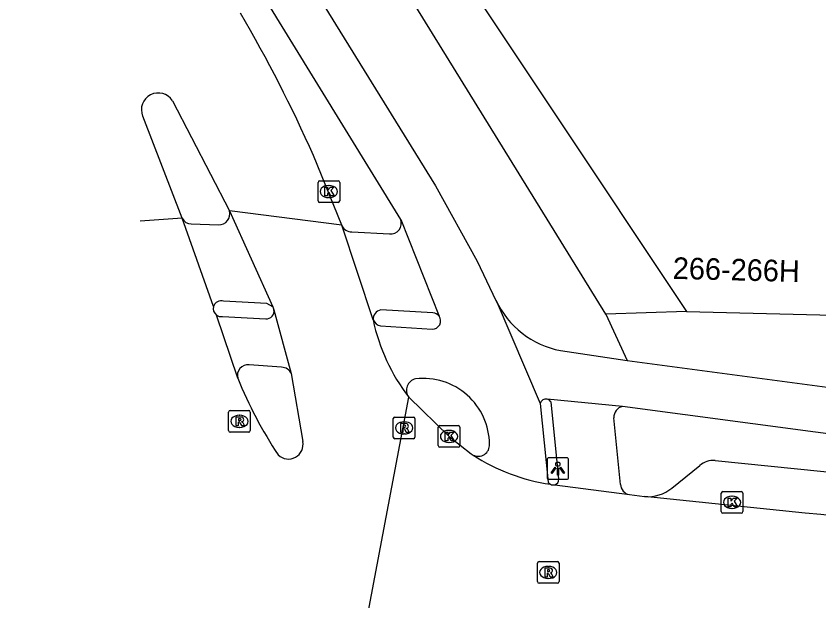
# Model space of a CAD drawing. Extents: x 158087 to 159494, y 382905 to 383981.
# Drawn here: x 158116.14 to 158153.26, y 383217.91 to 383244.96 of the extents above; entities that cross this region are included whole.
import ezdxf

# ---------------------------------------------------------------- set-up
doc = ezdxf.new("R2010")
doc.units = 0
for name, color, linetype in [('IMGEO_Fietspad_gesloten', 7, 'Continuous'), ('IMGEO_Kolk', 7, 'Continuous'), ('IMGEO_Lichtpunt', 7, 'Continuous'), ('IMGEO_Pand', 7, 'Continuous'), ('IMGEO_Pand_nummerreeks', 7, 'Continuous'), ('IMGEO_Parkeervlak_open', 7, 'Continuous'), ('IMGEO_Rijbaan_lokaal_gesloten', 7, 'Continuous'), ('IMGEO_Rioolput', 7, 'Continuous'), ('IMGEO_Voetpad_open', 7, 'Continuous')]:
    doc.layers.add(name, color=color, linetype=linetype)

msp = doc.modelspace()

# ---------------------------------------------------------------- linework, layer by layer
at = {"layer": 'IMGEO_Fietspad_gesloten'}
for points in [[(158118.441, 383264.758), (158135.528, 383237.105), (158137.451, 383233.617), (158138.325, 383231.809)], [(158133.922, 383235.542), (158116.135, 383264.493)], [(158133.922, 383235.542), (158135.691, 383231.086)], [(158138.325, 383231.809), (158138.329, 383231.797), (158140.364, 383227.042)], [(158125.678, 383231.065), (158127.681, 383230.961)], [(158132.979, 383230.63), (158135.368, 383230.486)], [(158141.305, 383229.487), (158144.391, 383229.036)], [(158144.391, 383229.036), (158160.112, 383226.941)], [(158128.413, 383228.717), (158126.917, 383228.829)], [(158144.169, 383226.91), (158140.686, 383227.24)], [(158140.364, 383227.042), (158140.74, 383223.411)], [(158159.127, 383224.909), (158144.169, 383226.91)]]:
    msp.add_lwpolyline(points, dxfattribs=at)
for centre, radius, start, end in [((158142.087, 383233.564), 4.151, 205.007, 259.142), ((158127.716, 383231.309), 0.349, 264.2417, 10.9635), ((158125.616, 383231.424), 0.364, 232.9851, 279.8076), ((158133.12, 383231.148), 0.537, 207.0122, 254.7617), ((158135.394, 383230.859), 0.374, 266.0798, 37.3301), ((158126.861, 383228.339), 0.494, 83.4339, 195.5759), ((158128.41, 383228.223), 0.494, 23.7357, 89.6533), ((158134.958, 383225.13), 3.071, 0.5018, 96.498), ((158134.721, 383227.655), 0.537, 101.7854, 216.3307), ((158140.629, 383226.972), 0.274, 77.9971, 165.1782), ((158137.503, 383225.129), 0.526, 243.1997, 3.0642), ((158140.974, 383223.54), 0.268, 208.7973, 240.0793)]:
    msp.add_arc(centre, radius, start, end, dxfattribs=at)
at = {"layer": 'IMGEO_Kolk'}
for p, q in [((158130.097, 383236.414), (158130.097, 383237.266)), ((158130.172, 383237.34), (158131.024, 383237.34)), ((158130.585, 383237.12), (158130.61, 383237.12)), ((158131.098, 383237.266), (158131.098, 383236.414)), ((158130.608, 383236.56), (158130.583, 383236.56)), ((158131.024, 383236.34), (158130.172, 383236.34)), ((158135.728, 383226.019), (158136.58, 383226.019)), ((158135.653, 383225.093), (158135.653, 383225.945)), ((158136.141, 383225.799), (158136.166, 383225.799)), ((158136.654, 383225.945), (158136.654, 383225.093)), ((158136.164, 383225.239), (158136.139, 383225.239)), ((158136.58, 383225.019), (158135.728, 383225.019)), ((158148.74, 383222.045), (158148.74, 383222.897)), ((158148.815, 383222.971), (158149.667, 383222.971)), ((158149.228, 383222.751), (158149.253, 383222.751)), ((158149.741, 383222.897), (158149.741, 383222.045)), ((158149.667, 383221.971), (158148.815, 383221.971)), ((158149.251, 383222.191), (158149.226, 383222.191))]:
    msp.add_line(p, q, dxfattribs=at)
for points in [[(158130.097, 383236.414), (158130.097, 383237.266)], [(158130.172, 383237.34), (158131.024, 383237.34)], [(158131.098, 383237.266), (158131.098, 383236.414)], [(158130.418, 383237.04), (158130.541, 383237.04), (158130.541, 383236.889), (158130.671, 383237.04), (158130.835, 383237.04), (158130.689, 383236.889), (158130.842, 383236.64), (158130.69, 383236.64), (158130.605, 383236.804), (158130.541, 383236.737), (158130.541, 383236.64), (158130.418, 383236.64), (158130.418, 383237.04)], [(158131.024, 383236.34), (158130.172, 383236.34)], [(158135.728, 383226.019), (158136.58, 383226.019)], [(158135.653, 383225.093), (158135.653, 383225.945)], [(158135.974, 383225.719), (158136.097, 383225.719), (158136.097, 383225.568), (158136.227, 383225.719), (158136.391, 383225.719), (158136.245, 383225.568), (158136.398, 383225.319), (158136.246, 383225.319), (158136.161, 383225.483), (158136.097, 383225.416), (158136.097, 383225.319), (158135.974, 383225.319), (158135.974, 383225.719)], [(158136.654, 383225.945), (158136.654, 383225.093)], [(158136.58, 383225.019), (158135.728, 383225.019)], [(158148.74, 383222.045), (158148.74, 383222.897)], [(158148.815, 383222.971), (158149.667, 383222.971)], [(158149.061, 383222.671), (158149.184, 383222.671), (158149.184, 383222.52), (158149.314, 383222.671), (158149.478, 383222.671), (158149.332, 383222.52), (158149.485, 383222.271), (158149.333, 383222.271), (158149.248, 383222.435), (158149.184, 383222.368), (158149.184, 383222.271), (158149.061, 383222.271), (158149.061, 383222.671)], [(158149.741, 383222.897), (158149.741, 383222.045)], [(158149.667, 383221.971), (158148.815, 383221.971)]]:
    msp.add_lwpolyline(points, dxfattribs=at)
for centre, start, end in [((158130.174, 383237.264), 91.552, 178.448), ((158130.174, 383237.264), 91.552, 178.448), ((158131.022, 383237.264), 1.552, 88.448), ((158131.022, 383237.264), 1.552, 88.448), ((158130.174, 383236.416), 181.552, 268.448), ((158130.174, 383236.416), 181.552, 268.448), ((158131.022, 383236.416), 271.552, 358.448), ((158131.022, 383236.416), 271.552, 358.448), ((158135.73, 383225.943), 91.552, 178.448), ((158135.73, 383225.943), 91.552, 178.448), ((158136.578, 383225.943), 1.552, 88.448), ((158136.578, 383225.943), 1.552, 88.448), ((158135.73, 383225.095), 181.552, 268.448), ((158135.73, 383225.095), 181.552, 268.448), ((158136.578, 383225.095), 271.552, 358.448), ((158136.578, 383225.095), 271.552, 358.448), ((158148.817, 383222.895), 91.552, 178.448), ((158148.817, 383222.895), 91.552, 178.448), ((158149.665, 383222.895), 1.552, 88.448), ((158149.665, 383222.895), 1.552, 88.448), ((158148.817, 383222.047), 181.552, 268.448), ((158148.817, 383222.047), 181.552, 268.448), ((158149.665, 383222.047), 271.552, 358.448), ((158149.665, 383222.047), 271.552, 358.448)]:
    msp.add_arc(centre, 0.0765, start, end, dxfattribs=at)
for centre, major_axis, ratio, start_param, end_param in [((158130.584, 383236.84), (-0.387, 0.002), 0.722429, 4.712389, 7.853982), ((158130.609, 383236.84), (-0.39, 0.002), 0.717154, 1.570796, 4.712389), ((158136.14, 383225.519), (-0.387, 0.002), 0.722429, 4.712389, 7.853982), ((158136.165, 383225.519), (-0.39, 0.002), 0.717154, 1.570796, 4.712389), ((158149.227, 383222.471), (-0.387, 0.002), 0.722429, 4.712389, 7.853982), ((158149.252, 383222.471), (-0.39, 0.002), 0.717154, 1.570796, 4.712389)]:
    msp.add_ellipse(centre, major_axis=major_axis, ratio=ratio, start_param=start_param, end_param=end_param, dxfattribs=at)
at = {"layer": 'IMGEO_Lichtpunt'}
for p, q in [((158141.588, 383224.533), (158140.78, 383224.533)), ((158141.588, 383224.533), (158140.78, 383224.533)), ((158140.686, 383224.438), (158140.686, 383223.631)), ((158140.686, 383224.438), (158140.686, 383223.631)), ((158141.682, 383223.631), (158141.682, 383224.438)), ((158141.682, 383223.631), (158141.682, 383224.438)), ((158140.78, 383223.537), (158141.588, 383223.537)), ((158140.78, 383223.537), (158141.588, 383223.537))]:
    msp.add_line(p, q, dxfattribs=at)
for points in [[(158141.06, 383224.102), (158141.099, 383224.074), (158140.911, 383223.812), (158140.873, 383223.839), (158141.06, 383224.102)], [(158141.162, 383224.054), (158141.209, 383224.054), (158141.209, 383223.732), (158141.162, 383223.732), (158141.162, 383224.054)], [(158141.272, 383224.074), (158141.31, 383224.101), (158141.497, 383223.839), (158141.458, 383223.811), (158141.272, 383224.074)]]:
    msp.add_lwpolyline(points, dxfattribs=at)
msp.add_circle((158141.185, 383224.236), 0.0994, dxfattribs=at)
for centre, start, end in [((158140.78, 383224.438), 90, 180), ((158140.78, 383224.438), 90, 180), ((158141.588, 383224.438), 0, 90), ((158141.588, 383224.438), 0, 90), ((158140.78, 383223.631), 180, 270), ((158140.78, 383223.631), 180, 270), ((158141.588, 383223.631), 270, 0), ((158141.588, 383223.631), 270, 360)]:
    msp.add_arc(centre, 0.0946, start, end, dxfattribs=at)
at = {"layer": 'IMGEO_Pand'}
for points in [[(158139.526, 383253.098), (158138.355, 383252.86), (158133.459, 383251.844), (158134.686, 383250), (158147.132, 383231.289)], [(158147.132, 383231.289), (158155.144, 383231.088)]]:
    msp.add_lwpolyline(points, dxfattribs=at)
at = {"layer": 'IMGEO_Parkeervlak_open'}
for points in [[(158146.459, 383223.131), (158147.745, 383224.182)], [(158148.453, 383224.408), (158153.476, 383223.894), (158158.929, 383223.306)]]:
    msp.add_lwpolyline(points, dxfattribs=at)
for centre, radius, start, end in [((158148.392, 383223.378), 1.031, 86.5877, 128.8194), ((158145.337, 383224.515), 1.782, 265.3753, 309.0336)]:
    msp.add_arc(centre, radius, start, end, dxfattribs=at)
at = {"layer": 'IMGEO_Rijbaan_lokaal_gesloten'}
for points in [[(158123.369, 383241.035), (158126, 383235.945)], [(158123.817, 383235.606), (158121.989, 383240.327)], [(158131.191, 383235.28), (158129.884, 383238.502)], [(158126, 383235.945), (158128.003, 383231.508)], [(158131.191, 383235.28), (158126, 383235.945)], [(158123.817, 383235.606), (158121.873, 383235.473)], [(158125.263, 383231.52), (158123.817, 383235.606)], [(158132.642, 383230.904), (158131.191, 383235.28)], [(158128.003, 383231.508), (158128.059, 383231.375)], [(158128.059, 383231.375), (158128.862, 383228.422)], [(158126.385, 383228.206), (158125.397, 383231.133)], [(158128.862, 383228.422), (158129.394, 383225.287)], [(158131.519, 383212.645), (158134.288, 383227.337)], [(158134.288, 383227.337), (158136.154, 383225.519), (158137.179, 383224.714), (158137.266, 383224.659)], [(158141.042, 383223.284), (158144.493, 383222.829)], [(158144.493, 383222.829), (158145.193, 383222.739)], [(158152.618, 383221.978), (158145.193, 383222.739)]]:
    msp.add_lwpolyline(points, dxfattribs=at)
for centre, radius, start, end in [((158069.76, 383211.879), 65.755, 23.88364, 30.328), ((158122.71, 383240.62), 0.779, 32.193, 202.1266), ((158125.618, 383231.426), 0.367, 165.1727, 233.0244), ((158141.481, 383232.819), 9.044, 192.2269, 217.3153), ((158145.575, 383236.071), 20.739, 202.2865, 213.3653), ((158128.727, 383225.154), 0.68, 225.9579, 11.2771), ((158142.112, 383232.076), 8.86, 236.8432, 261.7534), ((158140.97, 383223.538), 0.264, 240.6663, 285.7156), ((158123.913, 382936.802), 286.617, 79.62285, 84.25205)]:
    msp.add_arc(centre, radius, start, end, dxfattribs=at)
at = {"layer": 'IMGEO_Rioolput'}
for p, q in [((158126.039, 383226.717), (158126.891, 383226.717)), ((158125.964, 383225.791), (158125.964, 383226.643)), ((158126.452, 383226.497), (158126.477, 383226.497)), ((158126.965, 383226.643), (158126.965, 383225.791)), ((158133.578, 383225.489), (158133.578, 383226.341)), ((158133.653, 383226.415), (158134.505, 383226.415)), ((158134.579, 383226.341), (158134.579, 383225.489)), ((158134.066, 383226.195), (158134.091, 383226.195)), ((158126.891, 383225.717), (158126.039, 383225.717)), ((158126.475, 383225.937), (158126.45, 383225.937)), ((158134.089, 383225.635), (158134.064, 383225.635)), ((158134.505, 383225.415), (158133.653, 383225.415)), ((158140.241, 383218.806), (158140.241, 383219.658)), ((158140.316, 383219.732), (158141.168, 383219.732)), ((158141.242, 383219.658), (158141.242, 383218.806)), ((158140.729, 383219.512), (158140.754, 383219.512)), ((158140.752, 383218.952), (158140.727, 383218.952)), ((158141.168, 383218.732), (158140.316, 383218.732))]:
    msp.add_line(p, q, dxfattribs=at)
for points in [[(158126.039, 383226.717), (158126.891, 383226.717)], [(158125.964, 383225.791), (158125.964, 383226.643)], [(158126.553, 383226.415), (158126.301, 383226.417), (158126.301, 383226.017)], [(158126.479, 383226.336), (158126.425, 383226.336), (158126.425, 383226.255)], [(158126.965, 383226.643), (158126.965, 383225.791)], [(158133.578, 383225.489), (158133.578, 383226.341)], [(158133.653, 383226.415), (158134.505, 383226.415)], [(158134.579, 383226.341), (158134.579, 383225.489)], [(158126.301, 383226.017), (158126.425, 383226.017), (158126.425, 383226.179), (158126.436, 383226.179)], [(158126.425, 383226.255), (158126.477, 383226.255)], [(158126.483, 383226.15), (158126.554, 383226.017), (158126.694, 383226.017), (158126.629, 383226.143)], [(158134.167, 383226.113), (158133.915, 383226.115), (158133.915, 383225.715)], [(158134.093, 383226.034), (158134.039, 383226.034), (158134.039, 383225.953)], [(158126.891, 383225.717), (158126.039, 383225.717)], [(158133.915, 383225.715), (158134.039, 383225.715), (158134.039, 383225.877), (158134.05, 383225.877)], [(158134.039, 383225.953), (158134.091, 383225.953)], [(158134.097, 383225.848), (158134.168, 383225.715), (158134.308, 383225.715), (158134.243, 383225.841)], [(158134.505, 383225.415), (158133.653, 383225.415)], [(158140.241, 383218.806), (158140.241, 383219.658)], [(158140.316, 383219.732), (158141.168, 383219.732)], [(158141.242, 383219.658), (158141.242, 383218.806)], [(158140.83, 383219.43), (158140.578, 383219.432), (158140.578, 383219.032)], [(158140.756, 383219.351), (158140.702, 383219.351), (158140.702, 383219.27)], [(158140.578, 383219.032), (158140.702, 383219.032), (158140.702, 383219.194), (158140.713, 383219.194)], [(158140.702, 383219.27), (158140.754, 383219.27)], [(158140.76, 383219.165), (158140.831, 383219.032), (158140.971, 383219.032), (158140.906, 383219.158)], [(158141.168, 383218.732), (158140.316, 383218.732)]]:
    msp.add_lwpolyline(points, dxfattribs=at)
for centre, radius, start, end in [((158126.041, 383226.641), 0.0765, 91.552, 178.448), ((158126.041, 383226.641), 0.0765, 91.552, 178.448), ((158126.889, 383226.641), 0.0765, 1.552, 88.448), ((158126.889, 383226.641), 0.0765, 1.552, 88.448), ((158126.485, 383226.24), 0.0964, 77.0061, 93.1865), ((158126.499, 383226.297), 0.0378, 276.6634, 79.6772), ((158126.552, 383226.305), 0.109, 350.3612, 89.416), ((158133.655, 383226.339), 0.0765, 91.552, 178.448), ((158133.655, 383226.339), 0.0765, 91.552, 178.448), ((158134.503, 383226.339), 0.0765, 1.552, 88.448), ((158134.503, 383226.339), 0.0765, 1.552, 88.448), ((158126.435, 383226.126), 0.0533, 26.0293, 88.6989), ((158126.461, 383226.444), 0.19, 274.7715, 282.9687), ((158126.55, 383226.305), 0.112, 277.5842, 350.9817), ((158126.534, 383226.09), 0.108, 29.5134, 73.7905), ((158134.099, 383225.938), 0.0964, 77.0061, 93.1865), ((158134.113, 383225.995), 0.0378, 276.6634, 79.6772), ((158134.166, 383226.003), 0.109, 350.3612, 89.416), ((158134.164, 383226.003), 0.112, 277.5842, 350.9817), ((158126.041, 383225.793), 0.0765, 181.552, 268.448), ((158126.041, 383225.793), 0.0765, 181.552, 268.448), ((158126.889, 383225.793), 0.0765, 271.552, 358.448), ((158126.889, 383225.793), 0.0765, 271.552, 358.448), ((158134.049, 383225.824), 0.0533, 26.0293, 88.6989), ((158134.075, 383226.142), 0.19, 274.7715, 282.9687), ((158134.148, 383225.788), 0.108, 29.5134, 73.7905), ((158133.655, 383225.491), 0.0765, 181.552, 268.448), ((158133.655, 383225.491), 0.0765, 181.552, 268.448), ((158134.503, 383225.491), 0.0765, 271.552, 358.448), ((158134.503, 383225.491), 0.0765, 271.552, 358.448), ((158140.318, 383219.656), 0.0765, 91.552, 178.448), ((158140.318, 383219.656), 0.0765, 91.552, 178.448), ((158141.166, 383219.656), 0.0765, 1.552, 88.448), ((158141.166, 383219.656), 0.0765, 1.552, 88.448), ((158140.762, 383219.255), 0.0964, 77.0061, 93.1865), ((158140.776, 383219.312), 0.0378, 276.6634, 79.6772), ((158140.829, 383219.32), 0.109, 350.3612, 89.416), ((158140.827, 383219.32), 0.112, 277.5842, 350.9817), ((158140.712, 383219.141), 0.0533, 26.0293, 88.6989), ((158140.738, 383219.459), 0.19, 274.7715, 282.9687), ((158140.811, 383219.105), 0.108, 29.5134, 73.7905), ((158140.318, 383218.808), 0.0765, 181.552, 268.448), ((158140.318, 383218.808), 0.0765, 181.552, 268.448), ((158141.166, 383218.808), 0.0765, 271.552, 358.448), ((158141.166, 383218.808), 0.0765, 271.552, 358.448)]:
    msp.add_arc(centre, radius, start, end, dxfattribs=at)
for centre, major_axis, ratio, start_param, end_param in [((158126.451, 383226.217), (-0.387, 0.002), 0.722429, 4.712389, 7.853982), ((158126.476, 383226.217), (-0.39, 0.002), 0.717154, 1.570796, 4.712389), ((158134.065, 383225.915), (-0.387, 0.002), 0.722429, 4.712389, 7.853982), ((158134.09, 383225.915), (-0.39, 0.002), 0.717154, 1.570796, 4.712389), ((158140.728, 383219.232), (-0.387, 0.002), 0.722429, 4.712389, 7.853982), ((158140.753, 383219.232), (-0.39, 0.002), 0.717154, 1.570796, 4.712389)]:
    msp.add_ellipse(centre, major_axis=major_axis, ratio=ratio, start_param=start_param, end_param=end_param, dxfattribs=at)
at = {"layer": 'IMGEO_Voetpad_open'}
for points in [[(158143.404, 383231.17), (158123.051, 383264.159), (158120.641, 383268.4)], [(158124.236, 383235.344), (158125.499, 383235.299)], [(158131.666, 383234.972), (158133.404, 383234.886)], [(158128.003, 383231.508), (158127.725, 383231.66), (158125.733, 383231.774)], [(158135.409, 383231.233), (158133.006, 383231.367)], [(158147.132, 383231.289), (158143.404, 383231.17)], [(158143.404, 383231.17), (158144.391, 383229.036)], [(158141.234, 383223.543), (158141.179, 383224.035), (158140.869, 383227.098)], [(158144.08, 383223.303), (158143.773, 383226.382)]]:
    msp.add_lwpolyline(points, dxfattribs=at)
for centre, radius, start, end in [((158125.512, 383235.806), 0.507, 268.4814, 15.9285), ((158124.234, 383235.806), 0.462, 205.6601, 270.3045), ((158131.667, 383235.494), 0.522, 204.173, 269.9066), ((158133.452, 383235.381), 0.497, 264.5039, 18.9045), ((158125.617, 383231.427), 0.366, 71.4833, 165.2925), ((158133.069, 383230.943), 0.429, 98.4442, 185.2086), ((158135.393, 383230.858), 0.375, 37.4146, 87.5214), ((158140.623, 383226.97), 0.278, 27.5417, 76.8385), ((158144.304, 383226.396), 0.531, 104.7048, 181.5554), ((158140.969, 383223.539), 0.265, 285.9624, 0.9376), ((158144.581, 383223.322), 0.501, 182.1967, 259.9351)]:
    msp.add_arc(centre, radius, start, end, dxfattribs=at)

# ---------------------------------------------------------------- texts
at = {"layer": 'IMGEO_Pand_nummerreeks'}
msp.add_text('266-266H', height=1, rotation=358.5619, dxfattribs=at).set_placement((158146.489, 383232.805))

doc.saveas('drawing.dxf')
